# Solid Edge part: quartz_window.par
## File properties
Title: Quartz Window
Author: Lee
Template: Iso Part.par
Last saved by: Lee
Revision: 20
Application: Solid Edge
Material: Quartz Glass
Face Style: White (glass)
Coef. of Thermal Exp: 0.0
Thermal Conductivity: 0.0
Specific Heat: 0.0
Modulus of Elasticity: 0.0
Poisson's Ratio: 0.0
Yield Stress: 0.0
Ultimate Stress: 0.0
Elongation: 0.0
Manager: Garth Huber
Company: U of R Physics
Accuracy: 0.990
Document Number: 2
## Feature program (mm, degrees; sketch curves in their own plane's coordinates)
sketch for "unnamed Protrusion 1" plane through (0, 0, 0) normal (0, 0, 1) x-axis (1, 0, 0)
  circle centre (0, 0) radius 92
extrude "unnamed Protrusion 1" add finite 10 along +normal
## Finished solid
Body 1: solid body, 3 faces, 2 edges, 0 vertices.
  Faces by surface: plane 2, cylinder 1
  Edges by curve: circle 2
Bounding box of the edges (mm): 184.000 x 184.000 x 10.000, from (-92, -92, 0) to (92, 92, 10).
Cylindrical faces by radius (mm): R92 x1
Planar faces by outward normal: +z 1, -z 1
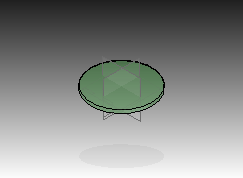
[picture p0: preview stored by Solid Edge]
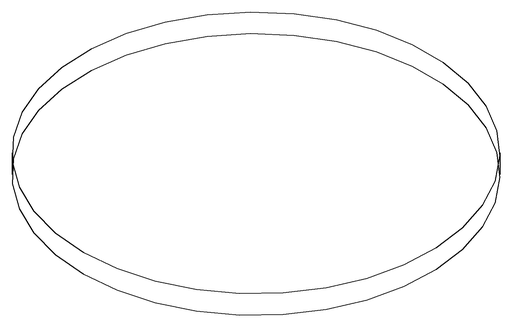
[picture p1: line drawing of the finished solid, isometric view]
